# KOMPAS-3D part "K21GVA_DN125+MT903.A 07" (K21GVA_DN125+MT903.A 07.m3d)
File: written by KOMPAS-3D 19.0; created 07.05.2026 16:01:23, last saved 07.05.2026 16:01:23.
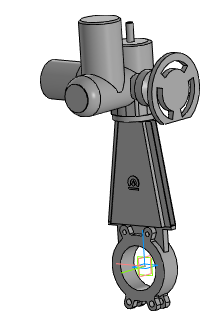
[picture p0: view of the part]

Document properties: Автор: Энергия; Полное имя файла: ..\K21GVA_DN50-DN1000+MT903.A\K21GVA_DN125+MT903.A 07.a3d

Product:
- Part/product: K21GVA_DN125+MT903.A 07
    Масса: 79.1301

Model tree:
1. Операция без истории:1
